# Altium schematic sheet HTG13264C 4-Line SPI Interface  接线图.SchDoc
size A4
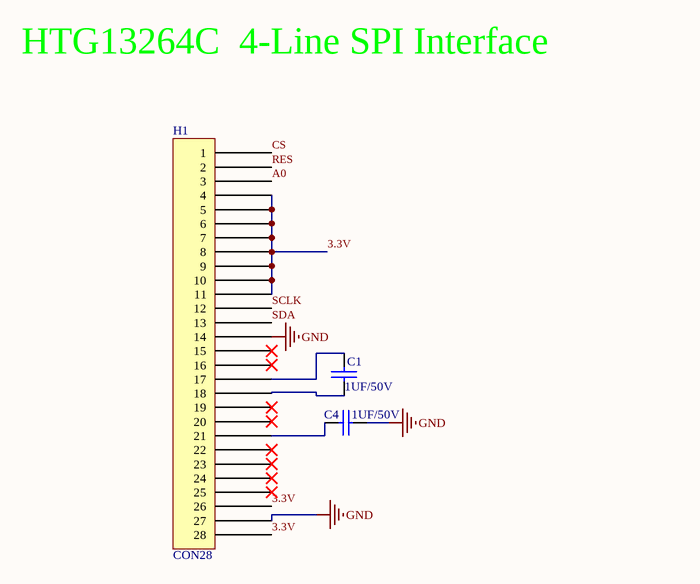
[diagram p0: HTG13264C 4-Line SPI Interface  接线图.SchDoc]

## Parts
C1  1UF/50V  [0805CAP]
C4  1UF/50V  [0805CAP]
H1  CON28

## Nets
GND: C4.1 H1.14 H1.27
3.3V: H1.4 H1.5 H1.6 H1.7 H1.8 H1.9 H1.10 H1.11 H1.26 H1.28
A0: H1.3
CS: H1.1
RES: H1.2
SCLK: H1.12
SDA: H1.13
NetC1_1: C1.1 H1.18
NetC1_2: C1.2 H1.17
NetC4_2: C4.2 H1.21

Not connected (* = marked no-connect by the designer): H1 15* 16* 19* 20* 22* 23* 24* 25*

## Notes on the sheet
- HTG13264C  4-Line SPI Interface

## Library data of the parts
C1 C4 = CAP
